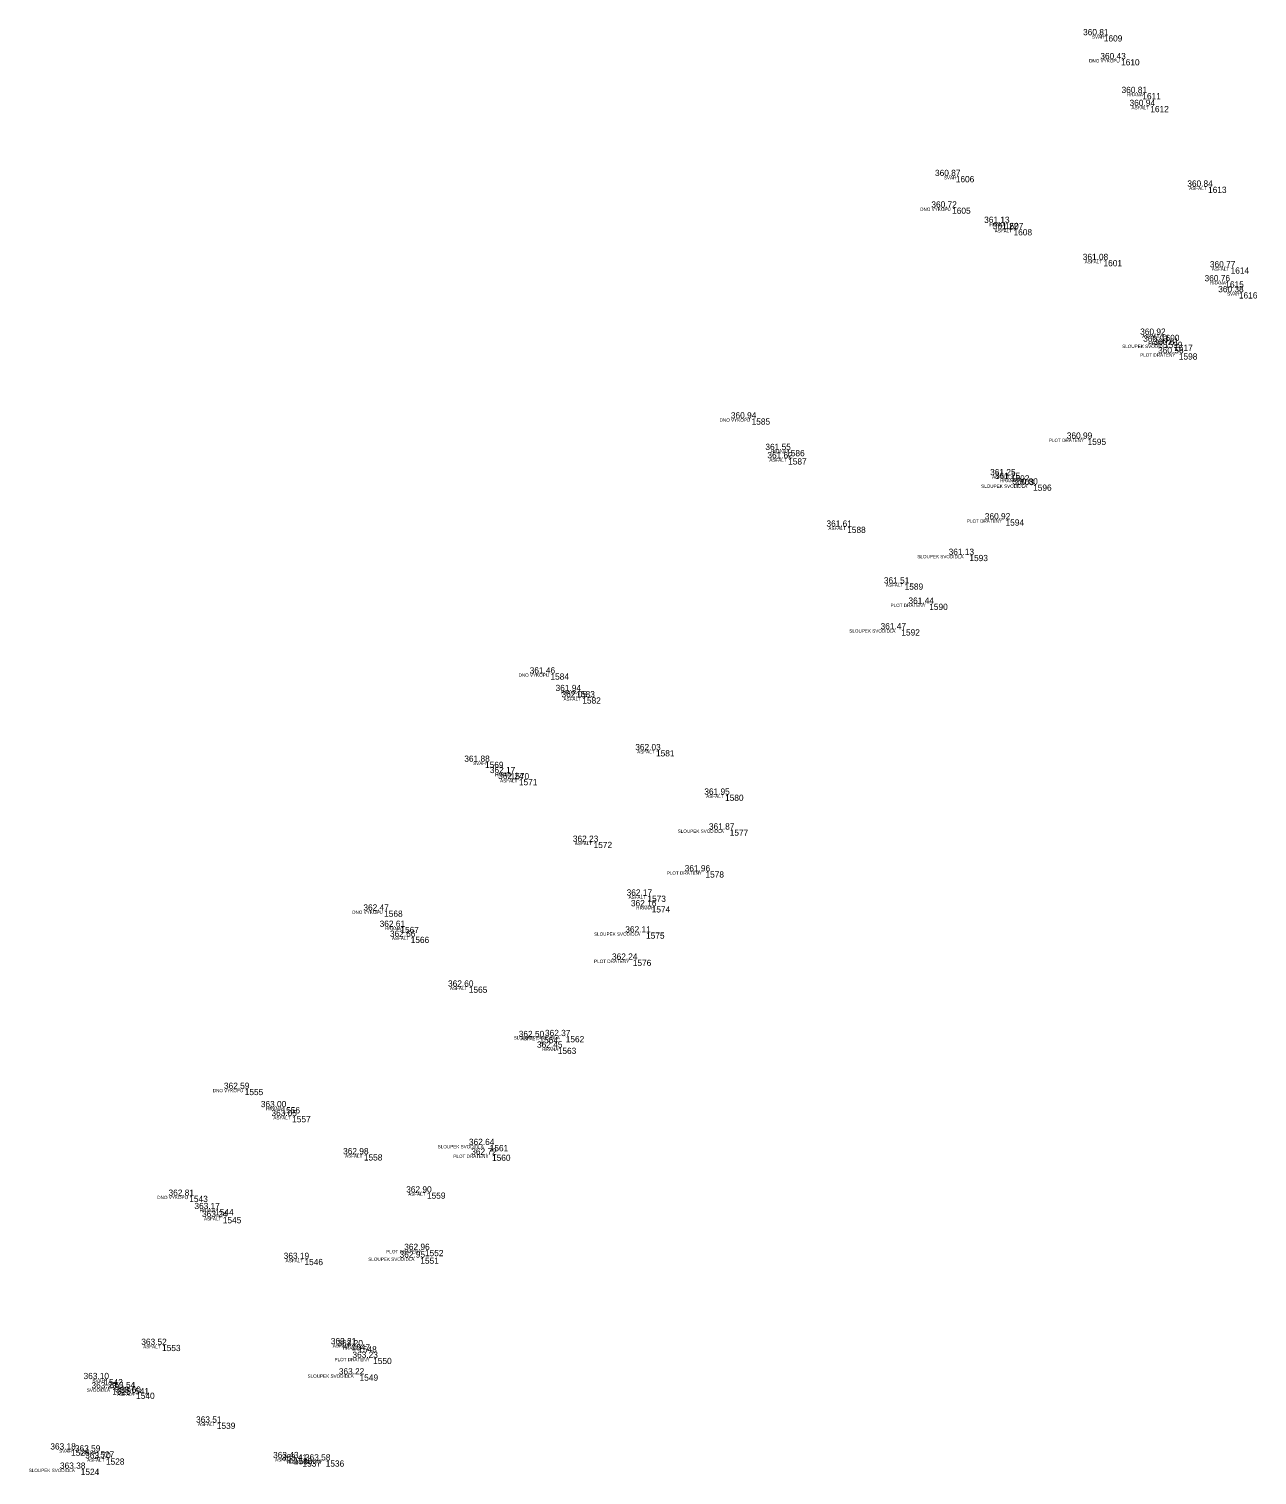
# Model space of a CAD drawing. Extents: x -597865 to -597551, y -1151663 to -1149883.
# Drawn here: x -597679.78 to -597642.78, y -1150383.9 to -1150340.35 of the extents above; entities that cross this region are included whole.
import ezdxf

# ---------------------------------------------------------------- set-up
doc = ezdxf.new("R2010")
doc.units = 0
for name, color, linetype in [('Vrstva 11', 7, 'Continuous'), ('Vrstva 12', 7, 'Continuous'), ('Vrstva 13', 7, 'Continuous'), ('Vrstva 14', 7, 'Continuous')]:
    doc.layers.add(name, color=color, linetype=linetype)

msp = doc.modelspace()

# ---------------------------------------------------------------- linework, layer by layer
at = {"layer": 'Vrstva 11'}
for p, q in [((-597647.4, -1150340.54), (-597647.4, -1150340.54)), ((-597646.88, -1150341.26), (-597646.88, -1150341.26)), ((-597646.24, -1150342.28), (-597646.24, -1150342.28)), ((-597646, -1150342.67), (-597646, -1150342.67)), ((-597651.86, -1150344.78), (-597651.86, -1150344.78)), ((-597644.26, -1150345.1), (-597644.26, -1150345.1)), ((-597651.97, -1150345.73), (-597651.97, -1150345.73)), ((-597650.38, -1150346.19), (-597650.38, -1150346.19)), ((-597650.12, -1150346.38), (-597650.12, -1150346.38)), ((-597647.41, -1150347.31), (-597647.41, -1150347.31)), ((-597643.58, -1150347.53), (-597643.58, -1150347.53)), ((-597643.74, -1150347.95), (-597643.74, -1150347.95)), ((-597643.33, -1150348.28), (-597643.33, -1150348.28)), ((-597645.68, -1150349.56), (-597645.68, -1150349.56)), ((-597645.59, -1150349.77), (-597645.59, -1150349.77)), ((-597645.28, -1150349.86), (-597645.28, -1150349.86)), ((-597645.14, -1150350.12), (-597645.14, -1150350.12)), ((-597658.01, -1150352.08), (-597658.01, -1150352.08)), ((-597656.97, -1150353.03), (-597656.97, -1150353.03)), ((-597647.89, -1150352.69), (-597647.89, -1150352.69)), ((-597656.91, -1150353.28), (-597656.91, -1150353.28)), ((-597650.2, -1150353.79), (-597650.2, -1150353.79)), ((-597650.06, -1150353.9), (-597650.06, -1150353.9)), ((-597649.53, -1150354.07), (-597649.53, -1150354.07)), ((-597650.36, -1150355.12), (-597650.36, -1150355.12)), ((-597655.13, -1150355.34), (-597655.13, -1150355.34)), ((-597651.45, -1150356.19), (-597651.45, -1150356.19)), ((-597653.4, -1150357.05), (-597653.4, -1150357.05)), ((-597652.66, -1150357.66), (-597652.66, -1150357.66)), ((-597653.5, -1150358.43), (-597653.5, -1150358.43)), ((-597664.07, -1150359.76), (-597664.07, -1150359.76)), ((-597663.29, -1150360.29), (-597663.29, -1150360.29)), ((-597663.11, -1150360.48), (-597663.11, -1150360.48)), ((-597660.89, -1150362.07), (-597660.89, -1150362.07)), ((-597666.04, -1150362.42), (-597666.04, -1150362.42)), ((-597665.27, -1150362.76), (-597665.27, -1150362.76)), ((-597665.02, -1150362.94), (-597665.02, -1150362.94)), ((-597658.81, -1150363.41), (-597658.81, -1150363.41)), ((-597658.67, -1150364.46), (-597658.67, -1150364.46)), ((-597662.77, -1150364.83), (-597662.77, -1150364.83)), ((-597659.4, -1150365.72), (-597659.4, -1150365.72)), ((-597661.15, -1150366.45), (-597661.15, -1150366.45)), ((-597669.08, -1150366.9), (-597669.08, -1150366.9)), ((-597661.02, -1150366.77), (-597661.02, -1150366.77)), ((-597668.59, -1150367.39), (-597668.59, -1150367.39)), ((-597668.28, -1150367.69), (-597668.28, -1150367.69)), ((-597661.19, -1150367.56), (-597661.19, -1150367.56)), ((-597661.59, -1150368.38), (-597661.59, -1150368.38)), ((-597666.53, -1150369.19), (-597666.53, -1150369.19)), ((-597664.4, -1150370.71), (-597664.4, -1150370.71)), ((-597663.61, -1150370.68), (-597663.61, -1150370.68)), ((-597663.85, -1150371.03), (-597663.85, -1150371.03)), ((-597673.28, -1150372.27), (-597673.28, -1150372.27)), ((-597672.17, -1150372.82), (-597672.17, -1150372.82)), ((-597671.85, -1150373.09), (-597671.85, -1150373.09)), ((-597665.9, -1150373.96), (-597665.9, -1150373.96)), ((-597669.69, -1150374.24), (-597669.69, -1150374.24)), ((-597665.83, -1150374.25), (-597665.83, -1150374.25)), ((-597674.95, -1150375.49), (-597674.95, -1150375.49)), ((-597667.79, -1150375.39), (-597667.79, -1150375.39)), ((-597674.17, -1150375.89), (-597674.17, -1150375.89)), ((-597673.94, -1150376.13), (-597673.94, -1150376.13)), ((-597671.48, -1150377.39), (-597671.48, -1150377.39)), ((-597667.99, -1150377.35), (-597667.99, -1150377.35)), ((-597667.85, -1150377.12), (-597667.85, -1150377.12)), ((-597675.77, -1150379.98), (-597675.77, -1150379.98)), ((-597670.06, -1150379.96), (-597670.06, -1150379.96)), ((-597669.86, -1150380.02), (-597669.86, -1150380.02)), ((-597669.41, -1150380.37), (-597669.41, -1150380.37)), ((-597669.82, -1150380.87), (-597669.82, -1150380.87)), ((-597677.51, -1150381.01), (-597677.51, -1150381.01)), ((-597677.27, -1150381.29), (-597677.27, -1150381.29)), ((-597676.72, -1150381.28), (-597676.72, -1150381.28)), ((-597676.55, -1150381.42), (-597676.55, -1150381.42)), ((-597674.12, -1150382.32), (-597674.12, -1150382.32)), ((-597678.51, -1150383.13), (-597678.51, -1150383.13)), ((-597677.77, -1150383.19), (-597677.77, -1150383.19)), ((-597677.46, -1150383.4), (-597677.46, -1150383.4)), ((-597671.8, -1150383.39), (-597671.8, -1150383.39)), ((-597671.54, -1150383.46), (-597671.54, -1150383.46)), ((-597670.84, -1150383.46), (-597670.84, -1150383.46)), ((-597678.22, -1150383.71), (-597678.22, -1150383.71))]:
    msp.add_line(p, q, dxfattribs=at)

# ---------------------------------------------------------------- texts
at = {"layer": 'Vrstva 12'}
for s, p in [('360.81 ', (-597648.025, -1150340.54)), ('360.43 ', (-597647.505, -1150341.26)), ('360.81 ', (-597646.865, -1150342.28)), ('360.94 ', (-597646.625, -1150342.67)), ('360.87 ', (-597652.485, -1150344.78)), ('360.84 ', (-597644.885, -1150345.1)), ('360.72 ', (-597652.595, -1150345.73)), ('361.13 ', (-597651.005, -1150346.19)), ('361.22 ', (-597650.745, -1150346.38)), ('361.08 ', (-597648.035, -1150347.31)), ('360.77 ', (-597644.205, -1150347.53)), ('360.76 ', (-597644.365, -1150347.95)), ('360.38 ', (-597643.955, -1150348.28)), ('360.92 ', (-597646.305, -1150349.56)), ('360.93 ', (-597646.215, -1150349.77)), ('360.61 ', (-597645.905, -1150349.86)), ('360.56 ', (-597645.765, -1150350.12)), ('360.94 ', (-597658.635, -1150352.08)), ('360.99 ', (-597648.515, -1150352.69)), ('361.55 ', (-597657.595, -1150353.03)), ('361.62 ', (-597657.535, -1150353.28)), ('361.25 ', (-597650.825, -1150353.79)), ('361.25 ', (-597650.685, -1150353.9)), ('360.80 ', (-597650.155, -1150354.07)), ('361.61 ', (-597655.755, -1150355.34)), ('360.92 ', (-597650.985, -1150355.12)), ('361.13 ', (-597652.075, -1150356.19)), ('361.51 ', (-597654.025, -1150357.05)), ('361.44 ', (-597653.285, -1150357.66)), ('361.47 ', (-597654.125, -1150358.43)), ('361.46 ', (-597664.695, -1150359.76)), ('361.94 ', (-597663.915, -1150360.29)), ('362.05 ', (-597663.735, -1150360.48)), ('362.03 ', (-597661.515, -1150362.07)), ('361.88 ', (-597666.665, -1150362.42)), ('362.17 ', (-597665.895, -1150362.76)), ('362.24 ', (-597665.645, -1150362.94)), ('361.95 ', (-597659.435, -1150363.41)), ('361.87 ', (-597659.295, -1150364.46)), ('362.23 ', (-597663.395, -1150364.83)), ('361.96 ', (-597660.025, -1150365.72)), ('362.17 ', (-597661.775, -1150366.45)), ('362.47 ', (-597669.705, -1150366.9)), ('362.16 ', (-597661.645, -1150366.77)), ('362.61 ', (-597669.215, -1150367.39)), ('362.11 ', (-597661.815, -1150367.56)), ('362.66 ', (-597668.905, -1150367.69)), ('362.24 ', (-597662.215, -1150368.38)), ('362.60 ', (-597667.155, -1150369.19)), ('362.50 ', (-597665.025, -1150370.71)), ('362.45 ', (-597664.475, -1150371.03)), ('362.37 ', (-597664.235, -1150370.68)), ('362.59 ', (-597673.905, -1150372.27)), ('363.00 ', (-597672.795, -1150372.82)), ('363.05 ', (-597672.475, -1150373.09)), ('362.64 ', (-597666.525, -1150373.96)), ('362.98 ', (-597670.315, -1150374.24)), ('362.72 ', (-597666.455, -1150374.25)), ('362.90 ', (-597668.415, -1150375.39)), ('362.81 ', (-597675.575, -1150375.49)), ('363.17 ', (-597674.795, -1150375.89)), ('363.24 ', (-597674.565, -1150376.13)), ('362.96 ', (-597668.475, -1150377.12)), ('363.19 ', (-597672.105, -1150377.39)), ('362.95 ', (-597668.615, -1150377.35)), ('363.52 ', (-597676.395, -1150379.98)), ('363.21 ', (-597670.685, -1150379.96)), ('363.20 ', (-597670.485, -1150380.02)), ('363.23 ', (-597670.035, -1150380.37)), ('363.10 ', (-597678.135, -1150381.01)), ('363.22 ', (-597670.445, -1150380.87)), ('363.23 ', (-597677.895, -1150381.29)), ('363.54 ', (-597677.345, -1150381.28)), ('363.60 ', (-597677.175, -1150381.42)), ('363.51 ', (-597674.745, -1150382.32)), ('363.18 ', (-597679.135, -1150383.13)), ('363.59 ', (-597678.395, -1150383.19)), ('363.38 ', (-597678.845, -1150383.71)), ('363.70 ', (-597678.085, -1150383.4)), ('363.43 ', (-597672.425, -1150383.39)), ('363.41 ', (-597672.165, -1150383.46)), ('363.58 ', (-597671.465, -1150383.46))]:
    msp.add_text(s, height=0.1875, dxfattribs=at).set_placement(p)
at = {"layer": 'Vrstva 13'}
for s, p in [('1609', (-597647.4, -1150340.728)), ('1610', (-597646.88, -1150341.448)), ('1611', (-597646.24, -1150342.468)), ('1612', (-597646, -1150342.857)), ('1606', (-597651.86, -1150344.968)), ('1613', (-597644.26, -1150345.288)), ('1605', (-597651.97, -1150345.917)), ('1607', (-597650.38, -1150346.377)), ('1608', (-597650.12, -1150346.568)), ('1601', (-597647.41, -1150347.498)), ('1614', (-597643.58, -1150347.718)), ('1615', (-597643.74, -1150348.137)), ('1616', (-597643.33, -1150348.468)), ('1600', (-597645.68, -1150349.748)), ('1599', (-597645.59, -1150349.958)), ('1617', (-597645.28, -1150350.048)), ('1598', (-597645.14, -1150350.308)), ('1585', (-597658.01, -1150352.268)), ('1586', (-597656.97, -1150353.218)), ('1595', (-597647.89, -1150352.877)), ('1587', (-597656.91, -1150353.468)), ('1602', (-597650.2, -1150353.978)), ('1603', (-597650.06, -1150354.088)), ('1596', (-597649.53, -1150354.258)), ('1594', (-597650.36, -1150355.308)), ('1588', (-597655.13, -1150355.528)), ('1593', (-597651.45, -1150356.377)), ('1589', (-597653.4, -1150357.238)), ('1590', (-597652.66, -1150357.847)), ('1592', (-597653.5, -1150358.617)), ('1584', (-597664.07, -1150359.948)), ('1583', (-597663.29, -1150360.478)), ('1582', (-597663.11, -1150360.667)), ('1581', (-597660.89, -1150362.258)), ('1569', (-597666.04, -1150362.607)), ('1570', (-597665.27, -1150362.948)), ('1571', (-597665.02, -1150363.127)), ('1580', (-597658.81, -1150363.597)), ('1577', (-597658.67, -1150364.647)), ('1572', (-597662.77, -1150365.018)), ('1578', (-597659.4, -1150365.907)), ('1573', (-597661.15, -1150366.637)), ('1568', (-597669.08, -1150367.088)), ('1574', (-597661.02, -1150366.958)), ('1567', (-597668.59, -1150367.578)), ('1566', (-597668.28, -1150367.877)), ('1575', (-597661.19, -1150367.748)), ('1576', (-597661.59, -1150368.568)), ('1565', (-597666.53, -1150369.377)), ('1564', (-597664.4, -1150370.897)), ('1562', (-597663.61, -1150370.867)), ('1563', (-597663.85, -1150371.218)), ('1555', (-597673.28, -1150372.458)), ('1556', (-597672.17, -1150373.008)), ('1557', (-597671.85, -1150373.278)), ('1561', (-597665.9, -1150374.147)), ('1558', (-597669.69, -1150374.427)), ('1560', (-597665.83, -1150374.438)), ('1543', (-597674.95, -1150375.677)), ('1559', (-597667.79, -1150375.578)), ('1544', (-597674.17, -1150376.078)), ('1545', (-597673.94, -1150376.318)), ('1546', (-597671.48, -1150377.578)), ('1551', (-597667.99, -1150377.538)), ('1552', (-597667.85, -1150377.308)), ('1553', (-597675.77, -1150380.167)), ('1547', (-597670.06, -1150380.147)), ('1548', (-597669.86, -1150380.208)), ('1550', (-597669.41, -1150380.558)), ('1549', (-597669.82, -1150381.058)), ('1542', (-597677.51, -1150381.198)), ('1525', (-597677.27, -1150381.478)), ('1541', (-597676.72, -1150381.468)), ('1540', (-597676.55, -1150381.607)), ('1539', (-597674.12, -1150382.508)), ('1526', (-597678.51, -1150383.318)), ('1527', (-597677.77, -1150383.377)), ('1528', (-597677.46, -1150383.588)), ('1538', (-597671.8, -1150383.578)), ('1537', (-597671.54, -1150383.647)), ('1536', (-597670.84, -1150383.647)), ('1524', (-597678.22, -1150383.897))]:
    msp.add_text(s, height=0.1875, dxfattribs=at).set_placement(p)
at = {"layer": 'Vrstva 14'}
for s, p in [('SVAH', (-597647.758, -1150340.64)), ('DNO VYKOPU', (-597647.843, -1150341.36)), ('HRANA', (-597646.707, -1150342.38)), ('ASFALT', (-597646.567, -1150342.77)), ('SVAH', (-597652.218, -1150344.88)), ('ASFALT', (-597644.827, -1150345.2)), ('DNO VYKOPU', (-597652.932, -1150345.83)), ('HRANA', (-597650.847, -1150346.29)), ('ASFALT', (-597650.687, -1150346.48)), ('ASFALT', (-597647.977, -1150347.41)), ('ASFALT', (-597644.147, -1150347.63)), ('HRANA', (-597644.207, -1150348.05)), ('SVAH', (-597643.688, -1150348.38)), ('ASFALT', (-597646.247, -1150349.66)), ('SLOUPEK SVODIDLA', (-597646.847, -1150349.96)), ('HRANA', (-597646.057, -1150349.87)), ('PLOT DRATENY', (-597646.305, -1150350.22)), ('DNO VYKOPU', (-597658.973, -1150352.18)), ('HRANA', (-597657.437, -1150353.13)), ('PLOT DRATENY', (-597649.055, -1150352.79)), ('ASFALT', (-597657.477, -1150353.38)), ('ASFALT', (-597650.767, -1150353.89)), ('HRANA', (-597650.527, -1150354)), ('SLOUPEK SVODIDLA', (-597651.097, -1150354.17)), ('PLOT DRATENY', (-597651.525, -1150355.22)), ('ASFALT', (-597655.697, -1150355.44)), ('SLOUPEK SVODIDLA', (-597653.017, -1150356.29)), ('ASFALT', (-597653.967, -1150357.15)), ('PLOT DRATENY', (-597653.825, -1150357.76)), ('SLOUPEK SVODIDLA', (-597655.067, -1150358.53)), ('DNO VYKOPU', (-597665.032, -1150359.86)), ('HRANA', (-597663.757, -1150360.39)), ('ASFALT', (-597663.677, -1150360.58)), ('ASFALT', (-597661.457, -1150362.17)), ('SVAH', (-597666.398, -1150362.52)), ('HRANA', (-597665.737, -1150362.86)), ('ASFALT', (-597665.587, -1150363.04)), ('ASFALT', (-597659.377, -1150363.51)), ('SLOUPEK SVODIDLA', (-597660.237, -1150364.56)), ('ASFALT', (-597663.337, -1150364.93)), ('PLOT DRATENY', (-597660.565, -1150365.82)), ('ASFALT', (-597661.717, -1150366.55)), ('DNO VYKOPU', (-597670.042, -1150367)), ('HRANA', (-597661.487, -1150366.87)), ('HRANA', (-597669.057, -1150367.49)), ('ASFALT', (-597668.847, -1150367.79)), ('SLOUPEK SVODIDLA', (-597662.757, -1150367.66)), ('PLOT DRATENY', (-597662.755, -1150368.48)), ('ASFALT', (-597667.097, -1150369.29)), ('SLOUPEK SVODIDLA', (-597665.177, -1150370.78)), ('ASFALT', (-597664.967, -1150370.81)), ('HRANA', (-597664.317, -1150371.13)), ('DNO VYKOPU', (-597674.243, -1150372.37)), ('HRANA', (-597672.637, -1150372.92)), ('ASFALT', (-597672.417, -1150373.19)), ('SLOUPEK SVODIDLA', (-597667.467, -1150374.06)), ('ASFALT', (-597670.257, -1150374.34)), ('PLOT DRATENY', (-597666.995, -1150374.35)), ('DNO VYKOPU', (-597675.912, -1150375.59)), ('ASFALT', (-597668.357, -1150375.49)), ('HRANA', (-597674.637, -1150375.99)), ('ASFALT', (-597674.507, -1150376.23)), ('ASFALT', (-597672.047, -1150377.49)), ('SLOUPEK SVODIDLA', (-597669.557, -1150377.45)), ('PLOT DRATENY', (-597669.015, -1150377.22)), ('ASFALT', (-597676.337, -1150380.08)), ('ASFALT', (-597670.627, -1150380.06)), ('HRANA', (-597670.327, -1150380.12)), ('PLOT DRATENY', (-597670.575, -1150380.47)), ('SLOUPEK SVODIDLA', (-597671.387, -1150380.97)), ('SVODIDLA', (-597678.037, -1150381.39)), ('SVAH', (-597677.868, -1150381.11)), ('HRANA', (-597677.187, -1150381.38)), ('ASFALT', (-597677.117, -1150381.52)), ('ASFALT', (-597674.687, -1150382.42)), ('SVAH', (-597678.868, -1150383.23)), ('HRANA', (-597678.237, -1150383.29)), ('ASFALT', (-597678.027, -1150383.5)), ('ASFALT', (-597672.367, -1150383.49)), ('HRANA', (-597672.007, -1150383.56)), ('PLOT DRATENY', (-597672.005, -1150383.56)), ('SLOUPEK SVODIDLA', (-597679.787, -1150383.81))]:
    msp.add_text(s, height=0.1, dxfattribs=at).set_placement(p)

doc.saveas('drawing.dxf')
